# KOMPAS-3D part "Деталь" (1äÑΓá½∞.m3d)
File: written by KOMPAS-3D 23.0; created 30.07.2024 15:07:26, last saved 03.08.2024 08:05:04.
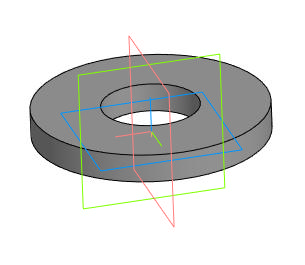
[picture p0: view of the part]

Document properties: Автор: zaytsev; Полное имя файла: C:\Users\zaytsev\Documents\1Деталь.m3d

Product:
- Part/product: Деталь
    Масса: 0.34355

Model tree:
1. Эскиз:1
2. Элемент выдавливания:1
     Расстояние 1 = 10
3. Осевая линия:1  (with: Элемент выдавливания:1)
